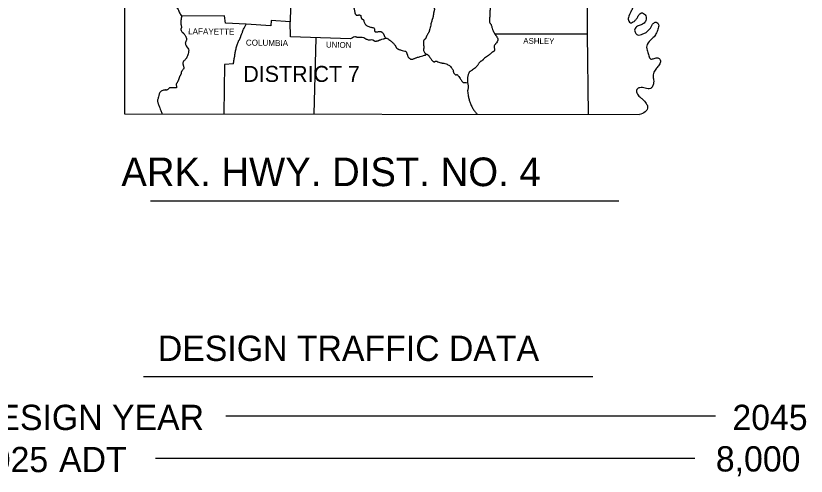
# Model space of a CAD drawing. Extents: x 6028666 to 6031787, y 5366484 to 5368484.
# Drawn here: x 6031098 to 6031661, y 5367489 to 5367817 of the extents above; entities that cross this region are included whole.
import ezdxf

# ---------------------------------------------------------------- set-up
doc = ezdxf.new("R2010")
doc.units = 0
doc.layers.add('2', color=7, linetype='Continuous')
doc.layers.add('Default', color=7, linetype='Continuous')

msp = doc.modelspace()

# ---------------------------------------------------------------- linework, layer by layer
at = {"layer": '2'}
for points in [[(6031504.85, 5367863.9), (6031504.85, 5367804.1), (6031505.65, 5367746.67)], [(6031294.75, 5367863.1), (6031293.45, 5367812.7), (6031279.95, 5367813.6), (6031279.85, 5367809.9), (6031262.06, 5367810.95)], [(6031175.45, 5367828.1), (6031175.65, 5367747.21), (6031542.15, 5367746.61)], [(6031246.65, 5367817), (6031216.35, 5367816.7)], [(6031262.06, 5367810.95), (6031247.35, 5367811.8), (6031246.65, 5367817)], [(6031336.35, 5367800.5), (6031293.65, 5367802.1), (6031293.45, 5367812.7)], [(6031439.2, 5367804.2), (6031504.85, 5367804.2)], [(6031311.86, 5367801.42), (6031310.27, 5367746.99)], [(6031253.05, 5367782.7), (6031246.85, 5367782.3), (6031246.17, 5367747.09)]]:
    msp.add_lwpolyline(points, dxfattribs=at)
for points in [[(6031557.45, 5367884.4), (6031556.45, 5367882.1), (6031555.35, 5367878.1), (6031555.65, 5367874.7), (6031557.15, 5367871.8), (6031559.55, 5367870.2), (6031562.15, 5367867.9), (6031561.95, 5367864.4), (6031560.45, 5367863.1), (6031556.95, 5367864), (6031554.25, 5367865.2), (6031551.95, 5367864.5), (6031548.85, 5367863), (6031546.55, 5367862.7), (6031546.65, 5367857.9), (6031549.75, 5367854.5), (6031552.45, 5367854.5), (6031555.55, 5367854.1), (6031556.65, 5367850.5), (6031554.85, 5367847.5), (6031551.85, 5367846), (6031548.05, 5367847.8), (6031545.35, 5367849.7), (6031542.65, 5367851.5), (6031539.25, 5367852.4), (6031537.35, 5367852), (6031536.45, 5367847.8), (6031538.05, 5367844), (6031540.65, 5367841.4), (6031543.05, 5367838), (6031542.65, 5367835.5), (6031540.85, 5367834.8), (6031537.65, 5367834.1), (6031535.75, 5367833.1), (6031535.25, 5367832.3), (6031536.25, 5367828.9), (6031537.15, 5367825.2), (6031537.15, 5367822.4), (6031536.05, 5367819.8), (6031534.35, 5367815.8), (6031534.55, 5367813.2), (6031535.75, 5367812), (6031537.25, 5367812.4), (6031539.25, 5367813.8), (6031540.55, 5367815.4), (6031541.65, 5367817.4), (6031543.75, 5367819.1), (6031546.35, 5367817.6), (6031546.95, 5367814.5), (6031545.45, 5367811.8), (6031543.35, 5367810.6), (6031540.75, 5367809.6), (6031538.85, 5367807.4), (6031539.35, 5367804.8), (6031540.85, 5367803.4), (6031544.55, 5367804.1), (6031547.05, 5367805.2), (6031548.45, 5367806.6), (6031550.15, 5367808.3), (6031551.05, 5367810), (6031552.35, 5367811.8), (6031554.65, 5367812.3), (6031555.75, 5367810.8), (6031555.35, 5367807.4), (6031553.95, 5367804.2), (6031552.05, 5367801.5), (6031549.95, 5367799.6), (6031547.35, 5367795.5), (6031547.85, 5367791.7), (6031548.85, 5367788.6), (6031550.25, 5367786.2), (6031552.65, 5367786.7), (6031555.35, 5367787), (6031556.95, 5367785.7), (6031556.75, 5367782.9), (6031554.75, 5367780.2), (6031552.85, 5367777.61), (6031551.85, 5367774.01), (6031552.25, 5367771.51), (6031552.25, 5367769.21), (6031551.45, 5367766.71), (6031550.05, 5367765.31), (6031546.35, 5367765.41), (6031542.45, 5367765.81), (6031540.35, 5367764.61), (6031540.75, 5367761.21), (6031543.05, 5367758.71), (6031544.65, 5367757.41), (6031546.95, 5367754.61), (6031547.95, 5367752.31), (6031547.65, 5367750.31), (6031546.25, 5367748.61), (6031542.15, 5367746.61)], [(6031361.02, 5367867.21), (6031360.95, 5367864.11), (6031360.88, 5367862.55), (6031360.83, 5367861.78), (6031360.75, 5367861), (6031360.45, 5367859.44), (6031360.05, 5367857.9), (6031359.79, 5367856.48), (6031359.62, 5367855.78), (6031359.5, 5367855.44), (6031359.43, 5367855.27), (6031359.35, 5367855.1), (6031359.05, 5367854.64), (6031358.67, 5367854.24), (6031357.85, 5367853.5), (6031357.05, 5367852.71), (6031356.25, 5367851.9), (6031354.75, 5367850.1), (6031354.41, 5367849.57), (6031354.11, 5367849), (6031353.8, 5367848.44), (6031353.45, 5367847.9), (6031352.15, 5367846.5), (6031350.45, 5367845.1), (6031348.75, 5367844.1), (6031346.85, 5367843.2), (6031346.34, 5367843.04), (6031345.81, 5367842.94), (6031345.28, 5367842.85), (6031344.75, 5367842.7), (6031343.92, 5367842.28), (6031343.56, 5367841.98), (6031343.4, 5367841.8), (6031343.25, 5367841.6), (6031342.99, 5367841.02), (6031342.9, 5367840.4), (6031343.15, 5367839.2), (6031343.56, 5367838.35), (6031344.01, 5367837.51), (6031344.45, 5367836.67), (6031344.85, 5367835.8), (6031345.45, 5367834.2), (6031345.59, 5367833.74), (6031345.67, 5367833.26), (6031345.7, 5367832.78), (6031345.65, 5367832.3), (6031344.95, 5367831.2), (6031343.35, 5367830.3), (6031341.45, 5367829.2), (6031339.75, 5367828.2), (6031339.35, 5367827.88), (6031339.02, 5367827.47), (6031338.76, 5367827), (6031338.55, 5367826.5), (6031338.28, 5367825.35), (6031338.35, 5367824.2), (6031338.54, 5367823.53), (6031338.75, 5367822.85), (6031338.97, 5367822.18), (6031339.15, 5367821.5), (6031339.3, 5367820.71), (6031339.45, 5367819.9), (6031339.84, 5367818.49), (6031340.19, 5367817.87), (6031340.44, 5367817.61), (6031340.59, 5367817.5), (6031340.75, 5367817.4), (6031341, 5367817.35), (6031341.25, 5367817.39), (6031341.5, 5367817.46), (6031341.75, 5367817.5), (6031341.98, 5367817.52), (6031342.2, 5367817.55), (6031342.66, 5367817.62), (6031343.11, 5367817.6), (6031343.33, 5367817.53), (6031343.44, 5367817.48), (6031343.55, 5367817.4), (6031343.7, 5367817.17), (6031343.75, 5367816.9), (6031343.85, 5367816.4), (6031344.25, 5367815.1), (6031344.55, 5367814.77), (6031345, 5367814.55), (6031345.45, 5367814.33), (6031345.75, 5367814), (6031345.82, 5367813.76), (6031345.86, 5367813.51), (6031345.89, 5367813.25), (6031345.95, 5367813), (6031346.33, 5367812.03), (6031346.85, 5367811.1), (6031347.17, 5367810.7), (6031347.52, 5367810.34), (6031348.35, 5367809.8), (6031349.45, 5367809.4), (6031351.75, 5367808.7), (6031352.95, 5367808.4), (6031353.12, 5367808.32), (6031353.44, 5367807.84), (6031353.59, 5367806.87), (6031353.75, 5367805.95), (6031353.94, 5367805.64), (6031354.25, 5367805.5), (6031355.05, 5367805.51), (6031355.85, 5367805.6), (6031357.05, 5367805.8), (6031358.06, 5367805.76), (6031358.56, 5367805.59), (6031358.81, 5367805.46), (6031359.05, 5367805.3), (6031359.59, 5367804.74), (6031359.95, 5367804.1), (6031360.19, 5367803.61), (6031360.4, 5367803.11), (6031360.61, 5367802.6), (6031360.85, 5367802.1), (6031361.38, 5367801.34), (6031361.66, 5367801.04)], [(6031394.05, 5367852.7), (6031394.13, 5367851.15), (6031394.22, 5367849.6), (6031394.45, 5367846.5), (6031394.63, 5367845.74), (6031394.94, 5367845), (6031395.23, 5367844.26), (6031395.32, 5367843.89), (6031395.35, 5367843.5), (6031395.31, 5367842.71), (6031395.21, 5367841.91), (6031395.12, 5367841.11), (6031395.05, 5367840.3), (6031394.95, 5367837.2), (6031394.95, 5367834.4), (6031394.95, 5367831.7), (6031394.95, 5367828.9), (6031395.15, 5367826.9), (6031395.3, 5367826.17), (6031395.49, 5367825.45), (6031395.68, 5367824.73), (6031395.85, 5367824), (6031396.1, 5367822.65), (6031396.16, 5367821.98), (6031396.15, 5367821.3), (6031396.05, 5367820.65), (6031395.88, 5367820), (6031395.7, 5367819.35), (6031395.55, 5367818.7), (6031395.48, 5367818.11), (6031395.43, 5367817.5), (6031395.36, 5367816.9), (6031395.25, 5367816.3), (6031395.07, 5367815.7), (6031394.86, 5367815.1), (6031394.64, 5367814.51), (6031394.45, 5367813.9), (6031393.75, 5367811.2), (6031392.95, 5367807.7), (6031392.64, 5367806.54), (6031392.46, 5367805.97), (6031392.25, 5367805.4), (6031391.95, 5367804.78), (6031391.58, 5367804.19), (6031391.2, 5367803.6), (6031390.85, 5367803), (6031390.61, 5367802.46), (6031390.4, 5367801.91), (6031390.19, 5367801.35), (6031389.95, 5367800.8), (6031389.64, 5367800.43), (6031389.23, 5367800.13), (6031388.82, 5367799.82), (6031388.66, 5367799.63), (6031388.55, 5367799.4), (6031388.33, 5367798.21), (6031388.35, 5367797), (6031388.42, 5367796.45), (6031388.51, 5367795.9), (6031388.6, 5367795.35), (6031388.65, 5367794.8), (6031388.63, 5367794.31), (6031388.56, 5367793.81), (6031388.48, 5367793.3), (6031388.45, 5367792.8), (6031388.63, 5367791.84), (6031389.15, 5367790.9), (6031389.49, 5367790.5), (6031389.85, 5367790.11), (6031390.58, 5367789.61)], [(6031175.45, 5367828.1), (6031178.95, 5367829.6), (6031180.45, 5367829.1), (6031181.75, 5367827.8), (6031183.25, 5367827.8), (6031184.05, 5367829), (6031185.55, 5367829.1), (6031186.75, 5367829), (6031188.05, 5367829.8), (6031189.15, 5367830.3), (6031190.65, 5367830.8), (6031191.75, 5367831.2), (6031192.75, 5367832.3), (6031194.55, 5367833.2), (6031196.65, 5367833.9), (6031197.25, 5367834.9), (6031198.25, 5367835.3), (6031200.25, 5367835.2), (6031201.55, 5367835.8), (6031202.65, 5367835.3), (6031203.65, 5367834.6), (6031203.85, 5367832), (6031204.65, 5367830.6), (6031205.85, 5367828.1), (6031207.55, 5367826.8), (6031209.15, 5367825.5), (6031209.75, 5367824.7), (6031211.45, 5367823.2), (6031212.95, 5367822.7), (6031213.65, 5367821.6), (6031214.75, 5367819), (6031216.35, 5367816.7)], [(6031436.05, 5367823.6), (6031435.75, 5367820.5), (6031435.65, 5367817.6), (6031435.45, 5367814.8), (6031435.4, 5367813.75), (6031435.4, 5367813.23), (6031435.45, 5367812.7), (6031435.65, 5367812.1), (6031436, 5367811.54), (6031436.37, 5367810.99), (6031436.65, 5367810.4), (6031437.35, 5367808.2), (6031438.05, 5367806.3), (6031439.45, 5367803.8), (6031439.76, 5367803.32), (6031440.1, 5367802.86), (6031440.44, 5367802.39), (6031440.75, 5367801.9), (6031441.26, 5367800.56), (6031441.31, 5367799.86), (6031441.15, 5367799.2), (6031440.35, 5367797.8), (6031439.99, 5367797.27), (6031439.6, 5367796.75), (6031439.21, 5367796.23), (6031438.85, 5367795.7), (6031438.69, 5367794.79), (6031438.9, 5367793.75), (6031439.07, 5367792.73), (6031438.75, 5367791.9), (6031438.55, 5367791.72), (6031438.33, 5367791.57), (6031437.86, 5367791.29), (6031437.39, 5367791.01), (6031436.95, 5367790.7), (6031435.82, 5367789.69), (6031435.25, 5367789.18), (6031434.65, 5367788.7), (6031433.35, 5367787.8), (6031431.95, 5367786.9), (6031431.54, 5367786.55), (6031431.18, 5367786.13), (6031430.83, 5367785.7), (6031430.45, 5367785.3), (6031429.92, 5367784.91), (6031429.34, 5367784.58), (6031428.76, 5367784.23), (6031428.25, 5367783.8), (6031427.81, 5367783.22), (6031427.44, 5367782.57), (6031427.07, 5367781.92), (6031426.65, 5367781.3), (6031426.24, 5367780.8), (6031425.81, 5367780.3), (6031424.85, 5367779.41), (6031423.35, 5367778.41), (6031422.83, 5367778.09), (6031422.3, 5367777.78), (6031421.51, 5367777.29), (6031421.25, 5367777.11), (6031420.89, 5367776.7), (6031420.65, 5367776.2), (6031420.35, 5367775.11), (6031420.09, 5367774.18), (6031419.85, 5367773.26), (6031419.69, 5367772.34), (6031419.65, 5367771.41), (6031419.77, 5367770.05), (6031419.95, 5367768.71), (6031420.35, 5367766.31), (6031420.31, 5367765.56), (6031420.1, 5367764.81), (6031419.9, 5367764.06), (6031419.85, 5367763.31), (6031420.35, 5367760.01), (6031420.85, 5367757.41), (6031421.65, 5367755.11), (6031422.75, 5367752.51), (6031423.41, 5367751.28), (6031424.15, 5367750.11), (6031425.41, 5367748.4), (6031426.79, 5367746.79)], [(6031216.35, 5367816.7), (6031216.01, 5367815.42), (6031215.87, 5367814.6), (6031215.75, 5367813.8), (6031215.65, 5367811.5), (6031215.73, 5367810.82), (6031215.89, 5367810.14), (6031216.05, 5367809.47), (6031216.15, 5367808.8), (6031216.08, 5367808.47), (6031215.89, 5367808.15), (6031215.71, 5367807.83), (6031215.65, 5367807.5), (6031215.75, 5367807.02), (6031215.91, 5367806.55), (6031216.45, 5367805.6), (6031216.82, 5367805.18), (6031217.21, 5367804.82), (6031217.6, 5367804.48), (6031217.95, 5367804.1), (6031218.53, 5367803.34), (6031219.05, 5367802.5), (6031219.32, 5367801.93), (6031219.52, 5367801.35), (6031219.66, 5367800.78), (6031219.75, 5367800.2), (6031219.64, 5367799.55), (6031219.3, 5367798.9), (6031218.96, 5367798.25), (6031218.85, 5367797.6), (6031218.98, 5367796.93), (6031219.2, 5367796.25), (6031219.85, 5367794.9), (6031220.07, 5367794.63), (6031220.31, 5367794.41), (6031220.55, 5367794.18), (6031220.75, 5367793.9), (6031221.25, 5367792.3), (6031221.16, 5367791.53), (6031221, 5367790.75), (6031220.55, 5367789.2), (6031219.65, 5367786.9), (6031219.45, 5367786.58), (6031219.21, 5367786.29), (6031218.69, 5367785.74), (6031218.15, 5367785.19), (6031217.65, 5367784.6), (6031217.05, 5367783.5), (6031217.35, 5367782), (6031217.5, 5367781.4), (6031217.66, 5367780.8), (6031217.79, 5367780.2), (6031217.83, 5367779.9), (6031217.85, 5367779.75), (6031217.85, 5367779.61), (6031217.67, 5367779.24), (6031217.5, 5367779.07), (6031217.35, 5367778.91), (6031216.7, 5367778.06), (6031216.05, 5367777.21), (6031215.87, 5367776.77), (6031215.81, 5367776.27), (6031215.78, 5367775.77), (6031215.65, 5367775.31), (6031215.44, 5367774.9), (6031215.2, 5367774.51), (6031214.96, 5367774.11), (6031214.75, 5367773.71), (6031214.49, 5367772.99), (6031214.25, 5367772.26), (6031214.01, 5367771.52), (6031213.75, 5367770.81), (6031213.46, 5367770.19), (6031213.12, 5367769.59), (6031212.77, 5367769), (6031212.45, 5367768.41), (6031212.39, 5367767.65), (6031212.55, 5367766.76), (6031212.61, 5367766.01), (6031212.51, 5367765.79), (6031212.25, 5367765.71), (6031210.25, 5367765.71), (6031207.95, 5367765.71), (6031207.38, 5367765.5), (6031206.89, 5367765.03), (6031206.41, 5367764.53), (6031205.85, 5367764.21), (6031205.39, 5367764.15), (6031204.91, 5367764.15), (6031204.43, 5367764.16), (6031203.95, 5367764.11), (6031202.77, 5367763.79), (6031201.65, 5367763.21), (6031201.17, 5367762.8), (6031200.78, 5367762.35), (6031200.25, 5367761.31), (6031199.75, 5367759.21), (6031199.6, 5367758.71), (6031199.43, 5367758.21), (6031199.15, 5367757.21), (6031199.1, 5367756.36), (6031199.23, 5367755.5), (6031199.46, 5367754.64), (6031199.75, 5367753.81), (6031200.65, 5367751.41), (6031201.35, 5367749.51), (6031202.25, 5367747.16)], [(6031253.05, 5367782.7), (6031253.55, 5367785.9), (6031253.67, 5367786.53), (6031253.8, 5367787.16), (6031253.93, 5367787.78), (6031254.05, 5367788.4), (6031254.14, 5367789), (6031254.21, 5367789.6), (6031254.27, 5367790.21), (6031254.35, 5367790.8), (6031254.95, 5367793.5), (6031255.85, 5367796.4), (6031256.65, 5367798.8), (6031256.76, 5367799.03), (6031256.89, 5367799.25), (6031257.2, 5367799.66), (6031257.51, 5367800.06), (6031257.65, 5367800.28), (6031257.75, 5367800.5), (6031257.93, 5367801), (6031258.1, 5367801.5), (6031258.27, 5367802.01), (6031258.45, 5367802.5), (6031259.35, 5367804.9), (6031259.57, 5367805.53), (6031259.77, 5367806.17), (6031259.99, 5367806.8), (6031260.25, 5367807.4), (6031262.06, 5367810.95)], [(6031336.35, 5367800.5), (6031337.95, 5367801.6), (6031339.45, 5367802.2), (6031340.2, 5367802.07), (6031340.58, 5367801.98), (6031340.95, 5367801.9), (6031342.55, 5367801.7), (6031342.9, 5367801.72), (6031343.25, 5367801.79), (6031343.6, 5367801.87), (6031343.95, 5367801.9), (6031345.75, 5367801.6), (6031346.15, 5367801.4), (6031346.52, 5367801.16), (6031346.88, 5367800.92), (6031347.25, 5367800.7), (6031348.08, 5367800.25), (6031348.95, 5367800), (6031350.65, 5367800), (6031352.15, 5367800), (6031352.51, 5367799.88), (6031352.81, 5367799.59), (6031353.11, 5367799.29), (6031353.45, 5367799.1), (6031354.04, 5367799.02), (6031354.66, 5367799), (6031355.27, 5367799.06), (6031355.85, 5367799.2), (6031356.35, 5367799.4), (6031356.85, 5367799.61), (6031357.35, 5367799.82), (6031357.85, 5367800), (6031359.85, 5367800.6), (6031360.53, 5367800.81), (6031361.22, 5367800.98), (6031361.9, 5367801.05), (6031362.24, 5367801.01), (6031362.55, 5367800.9), (6031363.8, 5367800.13), (6031364.95, 5367799.2), (6031365.81, 5367798.52), (6031366.65, 5367797.8), (6031368.05, 5367796.2), (6031368.33, 5367795.77), (6031368.55, 5367795.31), (6031368.78, 5367794.85), (6031369.05, 5367794.4), (6031370.15, 5367793.4), (6031370.59, 5367793.18), (6031371.04, 5367792.99), (6031371.95, 5367792.7), (6031373.35, 5367792.4), (6031375.05, 5367791.9), (6031375.54, 5367791.77), (6031375.76, 5367791.67), (6031375.95, 5367791.5), (6031376.24, 5367791.06), (6031376.42, 5367790.58), (6031376.57, 5367790.08), (6031376.75, 5367789.6), (6031376.89, 5367789.27), (6031377.01, 5367788.95), (6031377.24, 5367788.29), (6031377.55, 5367787.64), (6031377.77, 5367787.32), (6031377.9, 5367787.16), (6031378.05, 5367787), (6031378.66, 5367786.51), (6031379.29, 5367786.18), (6031379.92, 5367786.04), (6031380.55, 5367786.1), (6031381.33, 5367786.37), (6031382.1, 5367786.7), (6031382.87, 5367787.03), (6031383.65, 5367787.3), (6031386.15, 5367788), (6031387.95, 5367788.6), (6031389.05, 5367789), (6031389.3, 5367789.05), (6031389.55, 5367789.06), (6031389.81, 5367789.06), (6031390.05, 5367789.1), (6031390.07, 5367789.12), (6031390.04, 5367789.14), (6031389.91, 5367789.2), (6031389.77, 5367789.26), (6031389.74, 5367789.28), (6031389.75, 5367789.3), (6031390.04, 5367789.44), (6031390.35, 5367789.56), (6031390.95, 5367789.6), (6031391.24, 5367789.49), (6031391.54, 5367789.31), (6031392.05, 5367788.8), (6031392.24, 5367788.53), (6031392.41, 5367788.25), (6031392.57, 5367787.97), (6031392.75, 5367787.7), (6031393.95, 5367786.1), (6031394.48, 5367785.4), (6031394.75, 5367785.05), (6031395.05, 5367784.7), (6031395.3, 5367784.5), (6031395.58, 5367784.36), (6031395.87, 5367784.26), (6031396.15, 5367784.2), (6031396.43, 5367784.29), (6031396.7, 5367784.53), (6031396.97, 5367784.75), (6031397.25, 5367784.8), (6031398.75, 5367784.3), (6031400.05, 5367783.8), (6031401.55, 5367783.4), (6031401.88, 5367783.36), (6031402.2, 5367783.35), (6031402.53, 5367783.34), (6031402.85, 5367783.3), (6031404.55, 5367782.9), (6031405.85, 5367782.2), (6031407.05, 5367781.5), (6031408.25, 5367780.2), (6031409.45, 5367778.21), (6031409.58, 5367777.82), (6031409.66, 5367777.41), (6031409.73, 5367777), (6031409.85, 5367776.61), (6031410.45, 5367775.71), (6031410.83, 5367775.34), (6031411.25, 5367775.01), (6031411.57, 5367774.95), (6031411.94, 5367775.04), (6031412.29, 5367775.11), (6031412.55, 5367775.01), (6031413.04, 5367774.36), (6031413.52, 5367773.71), (6031414.45, 5367772.41), (6031415.15, 5367771.41), (6031415.8, 5367770.44), (6031416.18, 5367770), (6031416.4, 5367769.79), (6031416.65, 5367769.61), (6031416.92, 5367769.52), (6031417.2, 5367769.55), (6031417.48, 5367769.6), (6031417.75, 5367769.61), (6031419.89, 5367769.2)]]:
    msp.add_spline(points, degree=3, dxfattribs=at)
at = {"layer": 'Default'}
for p, q in [((6031194.16, 5367685.21), (6031527.61, 5367685.21)), ((6031189.09, 5367560.1), (6031509.09, 5367560.1)), ((6031247.67, 5367531.98), (6031596.22, 5367531.98)), ((6031197.67, 5367501.98), (6031581.72, 5367501.98))]:
    msp.add_line(p, q, dxfattribs=at)

# ---------------------------------------------------------------- texts
at = {"layer": '2'}
for s, height, rotation, p in [('LAFAYETTE', 4.299, 359.1839, (6031220.85, 5367803.9)), ('COLUMBIA', 4.299, 359.2125, (6031261.95, 5367795.8)), ('UNION', 4.2, 358.9584, (6031318.95, 5367794.4)), ('ASHLEY', 4.2, 359.2361, (6031459.45, 5367797.1))]:
    msp.add_text(s, height=height, rotation=rotation, dxfattribs=at).set_placement(p)
msp.add_text('DISTRICT 7', height=11.4, dxfattribs=at).set_placement((6031260.15, 5367769.91))
at = {"layer": 'Default'}
for s, height, p in [('  ARK. HWY. DIST. NO. 4', 20.4, (6031158.12, 5367695.67)), ('DESIGN TRAFFIC DATA', 18, (6031199.29, 5367571.2)), ('DESIGN YEAR', 18, (6031067.67, 5367521.98)), ('2045', 18, (6031608.37, 5367521.98)), ('2025', 18, (6031067.67, 5367491.98)), (' ADT', 18, (6031122.27, 5367491.98)), ('8,000', 18, (6031596.58, 5367492.45))]:
    msp.add_text(s, height=height, dxfattribs=at).set_placement(p)

doc.saveas('drawing.dxf')
